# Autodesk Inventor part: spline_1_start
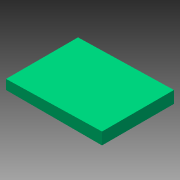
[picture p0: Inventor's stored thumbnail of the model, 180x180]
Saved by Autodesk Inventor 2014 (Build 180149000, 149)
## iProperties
Created: 2009-04
Part Number: spline_1_start
Document SubType Name: Modeling
Designer: PN
Density: 1 g/cm^3
Material: Generic
Appearance: 0,255,150 Green
Author: PN
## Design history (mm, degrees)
sketch "Sketch1"
  geometry: L1 (-70, 0)-(-70, -12); L2 (-70, -12)-(50, -12); L3 (50, -12)-(50, 3); L4 (50, 3)-(-70, 0); 2 further points
  constraints: 8 end point, 1 coincident, 1 horizontal alignment, 1 parallel, 1 perpendicular, 1 vertical
  dimensions: "d0" = 12 distance of L1.start L1.end; "d1" = 15 distance of L2.end L3.end; "d2" = 120 distance of L1.end L2.end; "d3" = 70 horizontal distance of point (0, 0) L1.end
extrude "Extrusion1" new body sketch "Sketch1" stored distance "d5" = 90; taper "d6" = 0 deg
workplane "Work Plane1"
sketch "GrillSketch" dims "d8" = 8.09017 (= 1.61803 x d9), "d9" = 5, "d10" = 10
  geometry: L1 (35.611, -25.369)-(35.611, -64.746); L2 (39.611, -25.369)-(39.611, -64.746); L3 (31.611, -25.369)-(31.611, -64.746); L4 (27.611, -25.369)-(27.611, -64.746); L5 (23.611, -25.369)-(23.611, -64.746); L6 (19.611, -25.369)-(19.611, -64.746); L7 (14.018, -50)-(46.09, -50); L8 (14.018, -55)-(46.09, -55); L9 (14.018, -60)-(46.09, -60); L10 (14.018, -45)-(46.09, -45); L11 (14.018, -40)-(46.09, -40); L12 (14.018, -35)-(46.09, -35); L13 (14.018, -30)-(46.09, -30); 3 further points; 1 other entity
  constraints: 26 end point, 1 horizontal, 1 horizontal alignment, 1 perpendicular, 2 other
  dimensions: "d11" = 15 distance from line of L13 point (29.611, -45); "d12" = 5 distance of L13.start L12.start; "d13" = 10 distance from line of L6 point (29.611, -45); "d14" = 4 distance of L6.start L5.start
sketch "EmbossSketch" dims "d15" = 16, "d16" = 11
  geometry: 3 further points; 1 other entity
  constraints: 2 horizontal alignment, 2 other
body "Solid1"
